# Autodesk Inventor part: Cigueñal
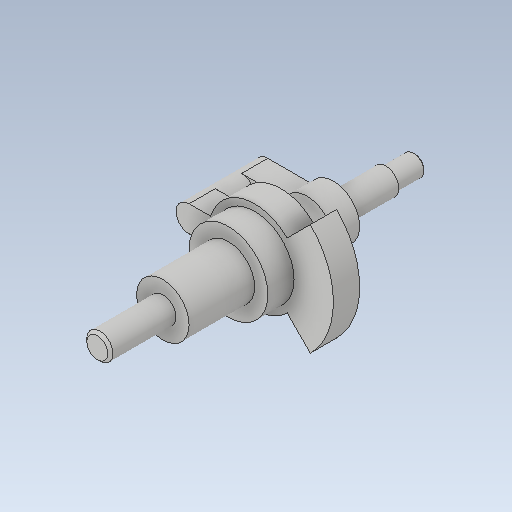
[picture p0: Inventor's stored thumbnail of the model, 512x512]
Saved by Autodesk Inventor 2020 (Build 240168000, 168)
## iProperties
Created: 2019-09
Part Number: Cigueñal
Material: Generic
Document SubType Name: Modeling
Designer: user
Density: 1 g/cm^3
Appearance: Default
Mass: 40.3064 g
Surface Area: 112.126 cm^2
Volume: 40.3064 cm^3
Author: user
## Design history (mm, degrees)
sketch "Sketch1"
  geometry: C1 r 5 at (0, 0); 1 further point
  constraints: 1 centre point, 1 coincident
  dimensions: "d0" = 10 diameter of C1
extrude "Extrusion1" new body sketch "Sketch1" distance "d1" = 25; taper "d2" = 0 deg
chamfer "Chamfer1" distance "d3" = 1; stored, may be unused: second distance "d4" = 2, angle "d5" = 45 deg
sketch "Sketch2"
  geometry: C1 r 10 at (0, 0); 1 further point
  constraints: 1 centre point, 1 coincident
  dimensions: "d6" = 20 diameter of C1
extrude "Extrusion2" join sketch "Sketch2" distance "d7" = 25; taper "d8" = 0 deg
sketch "Sketch3"
  geometry: C1 r 15 at (0, 0); 1 further point
  constraints: 1 centre point, 1 coincident
  dimensions: "d9" = 30 diameter of C1
extrude "Extrusion3" join sketch "Sketch3" distance "d10" = 10; taper "d11" = 0 deg
sketch "Sketch4"
  geometry: L1 (25, 5)-(16.771, 5); L2 (25, -5)-(16.771, -5); L3 (-12.374, -12.374)-(-21.213, -21.213); L4 (0, 0)-(30, 0); L5 (-12.374, 12.374)-(-21.213, 21.213); A1 r 5 centre (25, 0) between (25, -5) and (25, 5); A2 r 30 centre (0, 0) between (-21.213, 21.213) and (-21.213, -21.213); A3 r 17.5 centre (0, 0) between (16.771, 5) and (-12.374, 12.374); A4 r 17.5 centre (0, 0) between (-12.374, -12.374) and (16.771, -5); 1 further point
  constraints: 10 end point, 8 point on circle, 4 centre point, 2 coincident, 2 horizontal, 1 parallel, 1 tangent
  dimensions: "d13" = 10 diameter of A1; "d14" = 25 distance of point (0, 0) A1.centre; "d15" = 135 deg angle of L3 L4
extrude "Extrusion4" join sketch "Sketch4" distance "d16" = 10; taper "d17" = 0 deg
sketch "Sketch5"
  geometry: C1 r 5 at (25, 0); A1 r 5 centre (25, 0) between (25, -5) and (25, 5) reference; 1 further point
  constraints: 1 centre point, 1 coincident
extrude "Extrusion5" join sketch "Sketch5" distance "d18" = 10; taper "d19" = 0 deg
sketch "Sketch6"
  geometry: L1 (0, 5)-(-16.34, 5); L2 (0, -5)-(-16.34, -5); L3 (-8.229, -5)-(0, -5) reference; A1 r 5 centre (0, 0) between (0, -5) and (0, 5); A2 r 10 centre (-25, 0) between (-16.34, 5) and (-16.34, -5); 1 further point
  constraints: 5 end point, 4 point on circle, 2 centre point, 1 coincident, 1 collinear, 1 horizontal
extrude "Extrusion6" join sketch "Sketch6" distance "d20" = 10; taper "d21" = 0 deg
sketch "Sketch7"
  geometry: C1 r 5 at (-25, 0); 1 further point
  constraints: 1 centre point, 1 coincident
extrude "Extrusion7" join sketch "Sketch7" distance "d22" = 20; taper "d23" = 0 deg
sketch "Sketch8"
  geometry: C1 r 5 at (0, 0) reference; C2 r 4 at (0, 0); 1 further point
  constraints: 1 centre point, 1 coincident
  dimensions: "d24" = 8 diameter of C2
extrude "Extrusion8" join sketch "Sketch8" distance "d25" = 11; taper "d26" = 0 deg
chamfer "Chamfer2" distance "d27" = 0.5; stored, may be unused: second distance "d28" = 2, angle "d29" = 45 deg
body "Solid1"
other parameters: "d12" = 35
